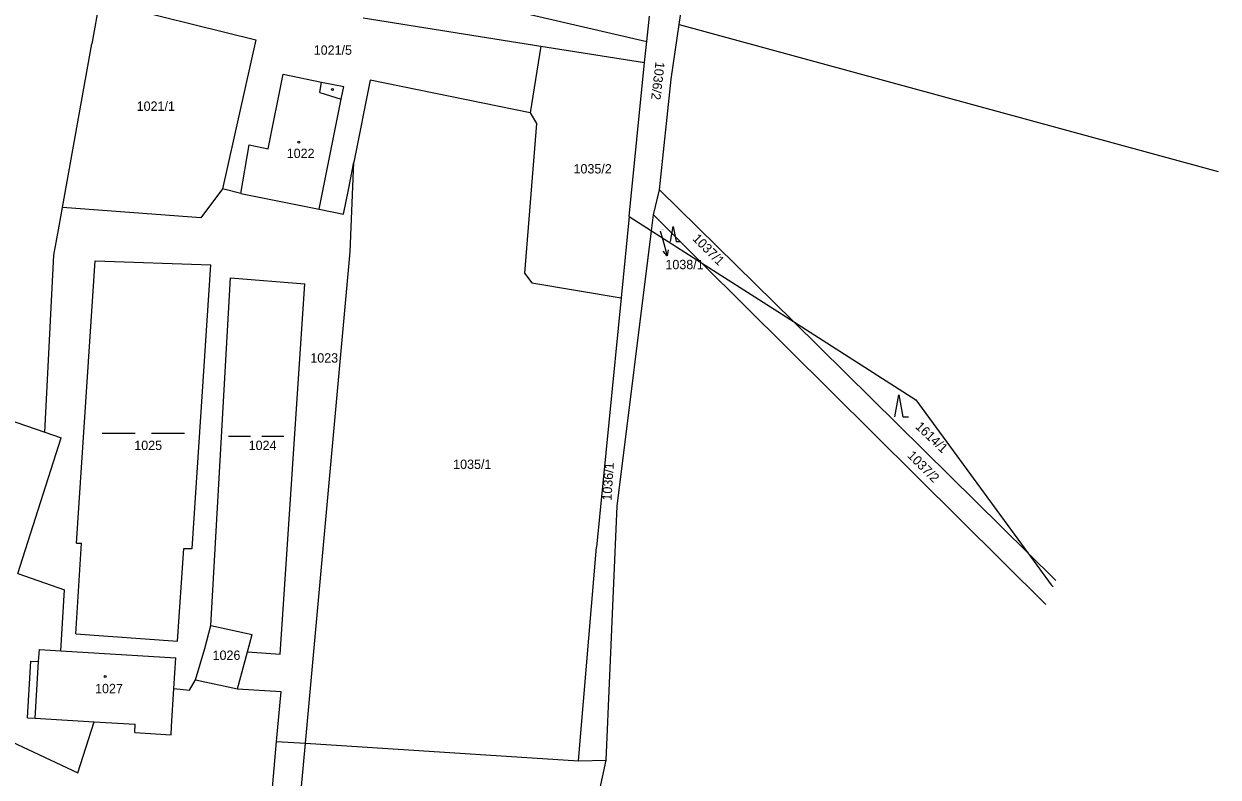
# Model space of a CAD drawing. Extents: x -779596 to -776743, y -1030330 to -1024513.
# Drawn here: x -777278.3 to -777061.2, y -1025939.4 to -1025802.5 of the extents above; entities that cross this region are included whole.
import ezdxf

# ---------------------------------------------------------------- set-up
doc = ezdxf.new("R2010")
doc.units = 0
for name, color, linetype in [('hranice parcel', 7, 'Continuous'), ('hranice vnitřní', 7, 'Continuous'), ('kultura', 7, 'Continuous'), ('č_ parcel šipka', 7, 'Continuous'), ('č_pacel stav_', 7, 'Continuous'), ('č_parcel poz_', 7, 'Continuous')]:
    doc.layers.add(name, color=color, linetype=linetype)

msp = doc.modelspace()

# ---------------------------------------------------------------- linework, layer by layer
at = {"layer": 'hranice parcel'}
for points in [[(-777159.13, -1025802.56), (-777156.7, -1025786.28)], [(-777215.03, -1025794.01), (-777165.05, -1025805.7)], [(-777264.52, -1025798.33), (-777265.91, -1025806.08)], [(-777264.52, -1025798.33), (-777236.13, -1025805.36)], [(-777165.05, -1025805.7), (-777164.54, -1025801.08)], [(-777216.58, -1025801.37), (-777184.3, -1025806.5)], [(-777160.62, -1025812.53), (-777159.13, -1025802.56)], [(-777159.13, -1025802.56), (-777061.167, -1025829.303)], [(-777236.13, -1025805.36), (-777242.16, -1025832.49)], [(-777271.27, -1025835.87), (-777265.91, -1025806.08)], [(-777184.3, -1025806.5), (-777186.23, -1025818.67)], [(-777184.3, -1025806.5), (-777165.46, -1025809.5)], [(-777165.46, -1025809.5), (-777165.05, -1025805.7)], [(-777168.23, -1025837.5), (-777165.46, -1025809.5)], [(-777233.86, -1025825.17), (-777231.13, -1025811.63)], [(-777231.13, -1025811.63), (-777224.15, -1025813.06)], [(-777224.15, -1025813.06), (-777220.11, -1025813.88)], [(-777220.57, -1025816.16), (-777220.11, -1025813.88)], [(-777215.3, -1025812.69), (-777218.26, -1025827.62)], [(-777186.23, -1025818.67), (-777215.3, -1025812.69)], [(-777162.69, -1025832.62), (-777160.62, -1025812.53)], [(-777224.6, -1025836.18), (-777220.57, -1025816.16)], [(-777185.07, -1025820.6), (-777187.27, -1025847.78)], [(-777186.23, -1025818.67), (-777185.07, -1025820.6)], [(-777238.85, -1025833.29), (-777237.31, -1025824.49)], [(-777237.31, -1025824.49), (-777233.86, -1025825.17)], [(-777219.26, -1025832.63), (-777218.26, -1025827.62)], [(-777218.93, -1025843.89), (-777218.26, -1025827.62)], [(-777242.16, -1025832.49), (-777246.11, -1025837.74)], [(-777238.85, -1025833.29), (-777242.16, -1025832.49)], [(-777238.85, -1025833.29), (-777224.6, -1025836.18)], [(-777220.16, -1025837.08), (-777219.26, -1025832.63)], [(-777163.84, -1025837.22), (-777162.69, -1025832.62)], [(-777162.69, -1025832.62), (-777138.38, -1025856.61)], [(-777271.88, -1025839.23), (-777271.27, -1025835.87)], [(-777246.11, -1025837.74), (-777271.27, -1025835.87)], [(-777224.6, -1025836.18), (-777220.16, -1025837.08)], [(-777168.23, -1025837.5), (-777169.69, -1025852.27)], [(-777168.23, -1025837.5), (-777164.19, -1025840.08)], [(-777164.19, -1025840.08), (-777163.84, -1025837.22)], [(-777163.84, -1025837.22), (-777155.08, -1025845.92)], [(-777272.83, -1025844.54), (-777271.88, -1025839.23)], [(-777170.39, -1025890.18), (-777164.19, -1025840.08)], [(-777164.19, -1025840.08), (-777155.08, -1025845.92)], [(-777274.45, -1025876.72), (-777272.83, -1025844.54)], [(-777227.08, -1025933.29), (-777218.93, -1025843.89)], [(-777268.71, -1025896.87), (-777265.33, -1025845.53)], [(-777265.33, -1025845.53), (-777244.28, -1025846.31)], [(-777247.66, -1025897.85), (-777244.28, -1025846.31)], [(-777155.08, -1025845.92), (-777092.512, -1025908.05)], [(-777155.08, -1025845.92), (-777138.38, -1025856.61)], [(-777244.31, -1025911.88), (-777240.73, -1025848.65)], [(-777240.73, -1025848.65), (-777227.17, -1025849.76)], [(-777187.27, -1025847.78), (-777185.92, -1025849.53)], [(-777231.71, -1025917.1), (-777227.17, -1025849.76)], [(-777185.92, -1025849.53), (-777169.69, -1025852.27)], [(-777169.69, -1025852.27), (-777174.18, -1025897.6)], [(-777138.38, -1025856.61), (-777095.77, -1025898.67)], [(-777138.38, -1025856.61), (-777116.13, -1025870.86)], [(-777116.13, -1025870.86), (-777095.77, -1025898.67)], [(-777283.15, -1025873.75), (-777274.45, -1025876.72)], [(-777274.45, -1025876.72), (-777271.49, -1025877.73)], [(-777279.37, -1025902.41), (-777271.49, -1025877.73)], [(-777172.43, -1025936.34), (-777170.39, -1025890.18)], [(-777268.81, -1025913.4), (-777267.79, -1025896.92)], [(-777268.71, -1025896.87), (-777267.79, -1025896.92)], [(-777250.36, -1025914.69), (-777249.22, -1025897.85)], [(-777249.22, -1025897.85), (-777247.66, -1025897.85)], [(-777177.43, -1025936.46), (-777174.18, -1025897.6)], [(-777095.77, -1025898.67), (-777090.671, -1025903.702)], [(-777095.77, -1025898.67), (-777091.52, -1025904.46)], [(-777279.37, -1025902.41), (-777270.91, -1025905.41)], [(-777271.55, -1025916.45), (-777270.91, -1025905.41)], [(-777091.52, -1025904.46), (-777091.151, -1025904.835)], [(-777245.35, -1025916.08), (-777244.31, -1025911.88)], [(-777244.31, -1025911.88), (-777236.78, -1025913.48)], [(-777268.81, -1025913.4), (-777250.36, -1025914.69)], [(-777237.64, -1025916.66), (-777236.78, -1025913.48)], [(-777275.6, -1025918.42), (-777275.46, -1025916.21)], [(-777275.46, -1025916.21), (-777271.55, -1025916.45)], [(-777247.08, -1025921.73), (-777245.35, -1025916.08)], [(-777277.64, -1025928.63), (-777277, -1025918.33)], [(-777277, -1025918.33), (-777275.6, -1025918.42)], [(-777271.55, -1025916.45), (-777250.66, -1025917.73)], [(-777251, -1025923.32), (-777250.66, -1025917.73)], [(-777239.46, -1025923.4), (-777237.64, -1025916.66)], [(-777237.64, -1025916.66), (-777231.71, -1025917.1)], [(-777248.19, -1025923.64), (-777247.08, -1025921.73)], [(-777247.08, -1025921.73), (-777239.46, -1025923.4)], [(-777251.42, -1025930.23), (-777251, -1025923.32)], [(-777251, -1025923.32), (-777248.19, -1025923.64)], [(-777239.46, -1025923.4), (-777231.52, -1025923.9)], [(-777232.32, -1025932.96), (-777231.52, -1025923.9)], [(-777277.64, -1025928.63), (-777276.23, -1025928.72)], [(-777276.23, -1025928.72), (-777265.5, -1025929.37)], [(-777268.47, -1025938.65), (-777265.5, -1025929.37)], [(-777265.5, -1025929.37), (-777258.02, -1025929.83)], [(-777258.11, -1025931.33), (-777258.02, -1025929.83)], [(-777258.11, -1025931.33), (-777251.51, -1025931.73)], [(-777251.51, -1025931.73), (-777251.42, -1025930.23)], [(-777282.55, -1025932.08), (-777268.47, -1025938.65)], [(-777235.26, -1025966.53), (-777232.32, -1025932.96)], [(-777232.32, -1025932.96), (-777227.08, -1025933.29)], [(-777230.26, -1025968.14), (-777227.08, -1025933.29)], [(-777227.08, -1025933.29), (-777177.43, -1025936.46)], [(-777181.34, -1025977.72), (-777172.43, -1025936.34)], [(-777177.43, -1025936.46), (-777172.43, -1025936.34)]]:
    msp.add_lwpolyline(points, dxfattribs=at)
at = {"layer": 'hranice vnitřní'}
for points in [[(-777224.45, -1025814.97), (-777224.15, -1025813.06)], [(-777224.45, -1025814.97), (-777220.57, -1025816.16)], [(-777276.23, -1025928.72), (-777275.6, -1025918.42)]]:
    msp.add_lwpolyline(points, dxfattribs=at)
at = {"layer": 'kultura'}
for points in [[(-777160.712, -1025842.02), (-777160.21, -1025839.339), (-777159.707, -1025842.02), (-777159.037, -1025842.02)], [(-777119.96, -1025873.93), (-777119.21, -1025869.93), (-777118.46, -1025873.93), (-777117.46, -1025873.93)], [(-777264.06, -1025876.92), (-777258.06, -1025876.92)], [(-777255.06, -1025876.92), (-777249.06, -1025876.92)], [(-777241.065, -1025877.43), (-777237.045, -1025877.43)], [(-777235.034, -1025877.43), (-777231.014, -1025877.43)]]:
    msp.add_lwpolyline(points, dxfattribs=at)
for centre in [(-777222.17, -1025814.42), (-777228.27, -1025823.99), (-777263.49, -1025921.12)]:
    msp.add_circle(centre, 0.175, dxfattribs=at)
at = {"layer": 'č_ parcel šipka'}
for points in [[(-777162.58, -1025840.11), (-777162.13, -1025841.74)], [(-777162.13, -1025841.74), (-777161.334, -1025844.632)], [(-777161.117, -1025843.535), (-777161.334, -1025844.632), (-777162.081, -1025843.8)]]:
    msp.add_lwpolyline(points, dxfattribs=at)

# ---------------------------------------------------------------- texts
msp.add_text('1038/1', height=1.7, dxfattribs=at).set_placement((-777161.64, -1025847.08))
at = {"layer": 'č_pacel stav_'}
for s, p in [('1022', (-777230.49, -1025826.86)), ('1027', (-777265.33, -1025924.18))]:
    msp.add_text(s, height=1.7, dxfattribs=at).set_placement(p)
at = {"layer": 'č_parcel poz_'}
for s, height, p in [('1021/5', 1.7, (-777225.579, -1025808.08)), ('1021/1', 1.7, (-777257.769, -1025818.28)), ('1035/2', 1.7, (-777178.349, -1025829.67)), ('1038/1', 0.1, (-777162.38, -1025839.91)), ('1023', 1.7, (-777226.2, -1025864.06)), ('1025', 1.7, (-777258.2, -1025879.96)), ('1024', 1.7, (-777237.41, -1025879.96)), ('1035/1', 1.7, (-777200.229, -1025883.4)), ('1026', 1.7, (-777243.966, -1025918.12))]:
    msp.add_text(s, height=height, dxfattribs=at).set_placement(p)
for s, rotation, p in [('1036/2', 263.20209, (-777163.436, -1025809.282)), ('1037/1', 315.00251, (-777156.858, -1025841.64)), ('1614/1', 316.60252, (-777116.338, -1025875.853)), ('1037/2', 315.00251, (-777117.788, -1025881.1)), ('1036/1', 86.30069, (-777171.456, -1025889.198))]:
    msp.add_text(s, height=1.7, rotation=rotation, dxfattribs=at).set_placement(p)

doc.saveas('drawing.dxf')
